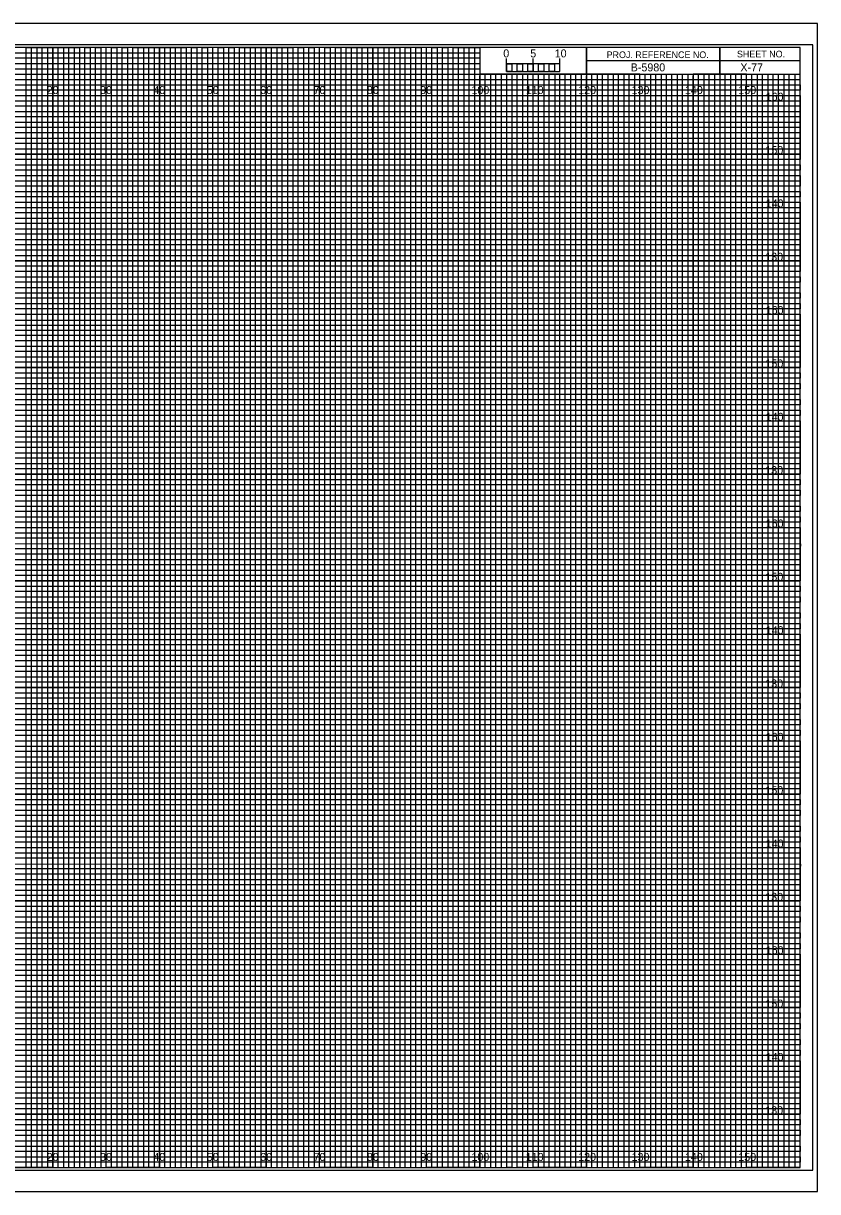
# Model space of a CAD drawing. Extents: x -13 to 323, y -5 to 434.
# Drawn here: x 174.5 to 323.3, y -4.5 to 214.5 of the extents above; entities that cross this region are included whole.
import ezdxf

# ---------------------------------------------------------------- set-up
doc = ezdxf.new("R2010")
doc.units = 0
for name, color, linetype in [('Exist Cross Section Cell', 7, 'Continuous'), ('Exist XS Center Line Elevation Label', 7, 'Continuous'), ('Exist XS Ground Line', 7, 'Continuous'), ('Prop CMT Guardrail Widen Shoulder', 7, 'Continuous'), ('Prop CMT Pvmt Course 1', 7, 'Continuous'), ('Prop CMT Pvmt Course 2', 7, 'Continuous'), ('Prop CMT Pvmt Course 3', 7, 'Continuous'), ('Prop CMT Pvmt Surface', 7, 'Continuous'), ('Prop CMT Pvmt Surface Shoulder', 7, 'Continuous'), ('Prop CMT Shld Paved Course 1', 7, 'Continuous'), ('Prop CMT Shld Paved Course 2', 7, 'Continuous'), ('Prop CMT Shld Paved Course 3', 7, 'Continuous'), ('Prop CMT Subgrade Earthwork', 7, 'Continuous'), ('Prop XS SE Text', 7, 'Continuous'), ('Scratch_Level_0', 7, 'Continuous')]:
    doc.layers.add(name, color=color, linetype=linetype)

msp = doc.modelspace()

# ---------------------------------------------------------------- linework, layer by layer
at = {"layer": 'Exist XS Center Line Elevation Label'}
for points in [[(165, 0), (175, 0), (175, 210), (185, 210), (185, 0), (195, 0), (195, 210), (205, 210), (205, 0), (215, 0), (215, 210), (225, 210), (225, 0), (235, 0), (235, 210), (245, 210), (245, 0), (255, 0), (255, 210), (259.93, 210), (260, 210), (260, 205), (264.99, 205), (264.99, 0), (275, 0), (275, 205), (285, 205), (285, 0), (295, 0), (295, 205), (305, 205), (305, 0), (315, 0), (315, 205)], [(0, 205), (275, 205)], [(0, 185), (320, 185), (320, 195), (0, 195)], [(0, 165), (320, 165), (320, 175), (0, 175)], [(0, 145), (320, 145), (320, 155), (0, 155)], [(0, 125), (320, 125), (320, 135), (0, 135)], [(0, 105), (320, 105), (320, 115), (0, 115)], [(0, 85), (320, 85), (320, 95), (0, 95)], [(0, 65), (320, 65), (320, 75), (0, 75)], [(0, 45), (320, 45), (320, 55), (0, 55)], [(0, 25), (320, 25), (320, 35), (0, 35)], [(0, 5), (320, 5), (320, 15), (0, 15)]]:
    msp.add_lwpolyline(points, dxfattribs=at)
at = {"layer": 'Exist XS Ground Line'}
for p, q in [((190, 210), (180, 210)), ((180, 210), (180, 0)), ((190, 0), (190, 210)), ((210, 210), (200, 210)), ((200, 210), (200, 0)), ((210, 0), (210, 210)), ((230, 210), (220, 210)), ((220, 210), (220, 0)), ((230, 0), (230, 210)), ((250, 210), (240, 210)), ((240, 210), (240, 0)), ((250, 0), (250, 210)), ((260, 210), (260, 0)), ((270, 0), (270, 205)), ((290, 205), (280, 205)), ((280, 205), (280, 0)), ((290, 0), (290, 205)), ((310, 205), (300, 205)), ((300, 205), (300, 0)), ((310, 0), (310, 205)), ((180, 0), (170, 0)), ((200, 0), (190, 0)), ((220, 0), (210, 0)), ((240, 0), (230, 0)), ((260, 0), (250, 0)), ((280, 0), (270, 0)), ((300, 0), (290, 0)), ((320, 0), (310, 0)), ((320, 0), (320, 0))]:
    msp.add_line(p, q, dxfattribs=at)
for points in [[(0, 200), (320, 200), (320, 190), (0, 190)], [(0, 180), (320, 180), (320, 170), (0, 170)], [(0, 160), (320, 160), (320, 150), (0, 150)], [(0, 140), (320, 140), (320, 130), (0, 130)], [(0, 120), (320, 120), (320, 110), (0, 110)], [(0, 100), (320, 100), (320, 90), (0, 90)], [(0, 80), (320, 80), (320, 70), (0, 70)], [(0, 60), (320, 60), (320, 50), (0, 50)], [(0, 40), (320, 40), (320, 30), (0, 30)], [(0, 20), (320, 20), (320, 10), (0, 10)]]:
    msp.add_lwpolyline(points, dxfattribs=at)
at = {"layer": 'Prop CMT Pvmt Course 2'}
for p, q in [((265, 205.49), (265, 207.9)), ((265, 206.9), (265, 207.9)), ((270, 205.49), (270, 207.9)), ((275, 205.49), (275, 207.9)), ((275, 206.9), (275, 207.9))]:
    msp.add_line(p, q, dxfattribs=at)
for points in [[(275, 206.9), (265, 206.9), (265, 205.49), (275, 205.49)], [(265, 206.9), (266, 206.9), (266, 205.49), (265, 205.49)], [(267, 206.9), (268, 206.9), (268, 205.49), (267, 205.49)], [(269, 206.9), (270, 206.9), (270, 205.49), (269, 205.49)], [(271, 206.9), (272, 206.9), (272, 205.49), (271, 205.49)], [(273, 206.9), (274, 206.9), (274, 205.49), (273, 205.49)]]:
    msp.add_lwpolyline(points, close=True, dxfattribs=at)
at = {"layer": 'Prop CMT Pvmt Course 3'}
msp.add_lwpolyline([(-13.4, -4.5), (323.3, -4.5), (323.3, 214.5), (-13.4, 214.5)], close=True, dxfattribs=at)
at = {"layer": 'Prop CMT Pvmt Surface'}
for p, q in [((180, 0), (180, 210)), ((190, 0), (190, 210)), ((200, 0), (200, 210)), ((210, 0), (210, 210)), ((220, 0), (220, 210)), ((230, 0), (230, 210)), ((240, 0), (240, 210)), ((250, 0), (250, 210)), ((260, 0), (260, 204.69)), ((270, 0), (270, 204.69)), ((280, 0), (280, 204.69)), ((290, 0), (290, 204.69)), ((300, 0), (300, 204.69)), ((310, 0), (310, 204.69)), ((0, 200), (320, 200)), ((0, 190), (320, 190)), ((0, 180), (320, 180)), ((0, 170), (320, 170)), ((0, 160), (320, 160)), ((0, 150), (320, 150)), ((0, 140), (320, 140)), ((0, 130), (320, 130)), ((0, 120), (320, 120)), ((0, 110), (320, 110)), ((0, 100), (320, 100)), ((0, 90), (320, 90)), ((0, 80), (320, 80)), ((0, 70), (320, 70)), ((0, 60), (320, 60)), ((0, 50), (320, 50)), ((0, 40), (320, 40)), ((0, 30), (320, 30)), ((0, 20), (320, 20)), ((0, 10), (320, 10))]:
    msp.add_line(p, q, dxfattribs=at)
at = {"layer": 'Prop CMT Pvmt Surface Shoulder'}
for p, q in [((323.3, 214.5), (-13.4, 214.5)), ((-13.4, -4.5), (323.3, -4.5))]:
    msp.add_line(p, q, dxfattribs=at)
at = {"layer": 'Prop CMT Shld Paved Course 1'}
for p, q in [((0, 209), (260, 209)), ((260, 209), (260, 207.98)), ((260, 207.98), (0, 207.98)), ((0, 207), (260, 207)), ((260, 205.89), (0, 205.89)), ((260, 207), (260, 205.89)), ((0, 204), (320, 204))]:
    msp.add_line(p, q, dxfattribs=at)
for points in [[(0, 203), (270, 203), (320, 203), (320, 202), (0, 202)], [(0, 201), (320, 201), (320, 199), (0, 199)], [(0, 198), (320, 198), (320, 197), (0, 196.98)], [(0, 196), (320, 196), (320, 194), (0, 194)], [(0, 193), (320, 193), (320, 192), (0, 192)], [(0, 191), (320, 191), (320, 189), (0, 189)], [(0, 188), (320, 188), (320, 187), (0, 187)], [(0, 186), (320, 186), (320, 184), (0, 184)], [(0, 183), (320, 183), (320, 182), (0, 182)], [(0, 181), (320, 181), (320, 179), (0, 179)], [(0, 178), (320, 178), (320, 177), (0, 177)], [(0, 176), (320, 176), (320, 173.95), (320, 173), (320, 172), (0, 172)], [(0, 174), (320, 174), (320, 173), (0, 173)], [(0, 171), (320, 171), (320, 169), (0, 169.03)], [(0, 169.03), (320, 169), (320, 168), (0, 168)], [(0, 167), (320, 167), (320, 166), (0, 166)], [(0, 164), (320, 164), (320, 163), (0, 163)], [(0, 162), (320, 162), (320, 161), (0, 161)], [(-0.07, 158.89), (320, 158.89), (320, 157.88), (-0.07, 157.88)], [(0, 157), (320, 157), (320, 156), (0, 156)], [(0, 154), (320, 154), (320, 153), (0, 153)], [(0, 152), (320, 152), (320, 151), (0, 151)], [(0, 149), (320, 149), (320, 148), (0, 148)], [(0, 147), (320, 147), (320, 146), (0, 146)], [(0, 144), (320, 144), (320, 143), (0, 143)], [(0, 142), (320, 142), (320, 141), (0, 141)], [(0, 139), (320, 139), (319.99, 137.98), (0, 138)], [(0, 137), (320, 137), (320, 136), (0, 136)], [(0, 134), (320, 134), (320, 133), (0, 133)], [(0, 132), (320, 132), (320, 131), (0, 131)], [(0, 129), (320, 129), (320, 128), (0, 128)], [(0, 127), (320, 127), (320, 126), (0, 126)], [(0, 124), (320, 124), (320, 123), (0, 123)], [(0, 122), (320, 122), (320, 121), (0, 121)], [(0, 119), (320, 119), (320, 118), (0, 118)], [(0, 116.99), (320.07, 116.91), (320, 116), (0, 116)], [(0, 114), (320, 114), (320, 113), (0, 113)], [(0, 112), (320, 112), (320, 111), (0, 111)], [(0, 109), (320, 109), (320, 108), (0, 108)], [(0, 107), (320, 107), (320, 106), (0, 106)], [(0, 104), (320, 104), (320, 103), (0, 103)], [(0, 102), (320, 102), (320, 101), (0, 101)], [(0, 99), (320, 99), (320, 98), (0, 98)], [(0, 97), (320, 97), (320, 96), (0, 96)], [(0, 94), (320, 94), (320, 93), (0, 93)], [(0, 92), (320, 92), (320, 91), (0, 91)], [(0, 89), (320, 89), (320, 88), (0, 88)], [(0, 87), (320, 87), (320, 86), (0, 86)], [(0, 84), (320, 84), (320, 83), (0, 83)], [(0, 82), (320, 82), (320, 81), (0, 81)], [(0, 79), (320, 79), (319.99, 77.98), (0, 78)], [(0, 77), (320, 77), (320, 76), (0, 76)], [(0, 74), (320, 74), (320, 73), (0, 73)], [(0, 72), (320, 72), (320, 71), (0, 71)], [(0, 69), (320, 69), (320, 68), (0, 68)], [(0, 67), (320, 67), (320, 66), (0, 66)], [(0, 64), (320, 64), (320, 63), (0, 63)], [(0, 62), (320, 62), (320, 61), (0, 61)], [(0, 59), (320, 59), (320, 58), (0, 58)], [(0, 56.99), (320.07, 56.91), (320, 56), (0, 56)], [(0, 54), (320, 54), (320, 53), (0, 53)], [(0, 52), (320, 52), (320, 51), (0, 51)], [(0, 49), (320, 49), (320, 48), (0, 48)], [(0, 47), (320, 47), (320, 46), (0, 46)], [(0, 44), (320, 44), (320, 43), (0, 43)], [(0, 42), (320, 42), (320, 41), (0, 41)], [(0, 39), (320, 39), (320, 38), (0, 38)], [(0, 37), (320, 37), (320, 36), (0, 36)], [(0, 34), (320, 34), (320, 33), (0, 33)], [(0, 32), (320, 32), (320, 31), (0, 31)], [(0, 29), (320, 29), (320, 28), (0, 28)], [(0, 27), (320, 27), (320, 26), (0, 26)], [(0, 24), (320, 24), (320, 23), (0, 23)], [(0, 22), (320, 22), (320, 21), (0, 21)], [(0, 19), (320, 19), (320, 18), (0, 18)], [(0, 17), (320, 17), (320, 16), (0, 16)], [(0, 14), (320, 14), (320, 13), (0, 13)], [(0, 12), (320, 12), (320, 11), (0, 11)], [(0, 9), (320, 9), (320, 8), (0, 8)], [(0, 7), (320, 7), (320, 6), (0, 6)], [(0, 4), (320, 4), (320, 3), (0, 3)], [(0, 2), (320, 2), (320, 1), (0, 1)]]:
    msp.add_lwpolyline(points, dxfattribs=at)
at = {"layer": 'Prop CMT Shld Paved Course 2'}
for p, q in [((305, 210), (305, 205)), ((305, 205), (305, 210)), ((280, 207.5), (280, 205)), ((320, 207.49), (280, 207.49)), ((280, 205), (320, 205))]:
    msp.add_line(p, q, dxfattribs=at)
for points in [[(320, 210), (0, 210), (0, 0), (320, 0)], [(280, 210), (260, 210), (260, 205.03), (280, 205.03)], [(320, 210), (280, 210), (280, 205), (320, 205)]]:
    msp.add_lwpolyline(points, close=True, dxfattribs=at)
at = {"layer": 'Prop CMT Shld Paved Course 3'}
for p, q in [((267, 205), (266.01, 205)), ((266.01, 205), (266.01, 0)), ((267, 0), (267, 205)), ((269, 205), (268, 205)), ((268, 205), (268, 0)), ((269, 0), (269, 205)), ((266.01, 0), (265, 0)), ((268, 0), (267, 0))]:
    msp.add_line(p, q, dxfattribs=at)
for points in [[(175, 0), (176, 0), (176, 210), (177, 210), (177, 0)], [(177, 0), (178, 0), (178, 210), (179, 210), (179, 0)], [(180, 0), (181, 0), (181, 210), (182, 210), (182, 0)], [(182, 0), (183, 0), (183, 210), (184, 210), (184, 0)], [(185, 0), (186, 0), (186, 210), (187, 210), (187, 0)], [(187, 0), (188, 0), (188, 210), (189, 210), (189, 0)], [(190, 0), (191, 0), (191, 210), (192, 210), (192, 0)], [(192, 0), (193, 0), (193, 210), (194, 210), (194, 0)], [(195, 0), (196, 0), (196, 210), (197, 210), (197, 0)], [(197, 0), (198, 0), (198, 210), (199, 210), (199, 0)], [(200, 0), (201, 0), (201, 210), (202, 210), (202, 0)], [(202, 0), (203, 0), (203, 210), (204, 210), (204, 0)], [(205, 0), (206, 0), (206, 210), (207, 210), (207, 0)], [(207, 0), (208, 0), (208, 210), (209, 210), (209, 0)], [(210, 0), (211, 0), (211, 210), (212, 210), (212, 0)], [(212, 0), (213, 0), (213, 210), (214, 210), (214, 0)], [(215, 0), (216, 0), (216, 210), (217, 210), (217, 0)], [(217, 0), (218, 0), (218, 210), (219, 210), (219, 0)], [(220, 0), (221, 0), (221, 210), (222, 210), (222, 0)], [(222, 0), (223, 0), (223, 210), (224, 210), (224, 0)], [(225, 0), (226, 0), (226, 210), (227, 210), (227, 0)], [(227, 0), (228, 0), (228, 210), (229, 210), (229, 0)], [(230, 0), (231, 0), (231, 210), (232, 210), (232, 0)], [(232, 0), (233, 0), (233, 210), (234, 210), (234, 0)], [(235, 0), (236, 0), (236, 210), (237, 210), (237, 0)], [(237, 0), (238, 0), (238, 210), (239, 210), (239, 0)], [(240, 0), (241, 0), (241, 210), (242, 210), (242, 0)], [(242, 0), (243, 0), (243, 210), (244, 210), (244, 0)], [(245, 0), (246, 0), (246, 210), (247, 210), (247, 0)], [(247, 0), (248, 0), (248, 210), (249, 210), (249, 0)], [(250, 0), (251, 0), (251, 210), (252, 210), (252, 0)], [(252, 0), (253, 0), (253, 210), (254, 210), (254, 0)], [(255, 0), (256, 0), (256, 210), (257, 210), (257, 0)], [(257, 0), (258, 0), (258, 210), (259, 210), (259, 0)], [(260, 0), (261, 0), (261, 205), (262.02, 205), (262.02, 0)], [(262, 0), (263, 0), (263, 205), (263.99, 205), (263.99, 0)], [(270, 0), (270.98, 0), (270.98, 205), (272, 205), (272, 0)], [(272, 0), (273, 0), (273, 205), (274.05, 205), (274.05, 0)], [(275, 0), (276, 0), (276, 205), (277, 205), (277, 0)], [(277, 0), (278, 0), (278, 205), (279, 205), (279, 0)], [(280, 0), (281, 0), (281, 205), (282, 205), (282, 0)], [(282, 0), (283, 0), (283, 205), (284, 205), (284, 0)], [(285, 0), (286, 0), (286, 205), (287, 205), (287, 0)], [(287, 0), (288, 0), (288, 205), (289, 205), (289, 0)], [(290, 0), (291, 0), (291, 205), (292, 205), (292, 0)], [(292, 0), (293, 0), (293, 205), (294, 205), (294, 0)], [(295, 0), (296, 0), (296, 205), (297, 205), (297, 0)], [(297, 0), (298, 0), (298, 205), (299, 205), (299, 0)], [(300, 0), (301, 0), (301, 205), (302, 205), (302, 0)], [(302, 0), (303, 0), (303, 205), (304, 205), (304, 0)], [(305, 0), (306, 0), (306, 205), (307, 205), (307, 0)], [(307, 0), (308, 0), (308, 205), (309, 205), (309, 0)], [(310, 0), (311, 0), (311, 205), (312, 205), (312, 0)], [(312, 0), (313, 0), (313, 205), (314, 205), (314, 0)], [(315, 0), (316, 0), (316, 205), (317, 205), (317, 0)], [(317, 0), (318, 0), (318, 205), (319, 205), (319, 0)]]:
    msp.add_lwpolyline(points, dxfattribs=at)
at = {"layer": 'Prop CMT Subgrade Earthwork'}
msp.add_lwpolyline([(-10.8, -0.5), (322.4, -0.5), (322.4, 210.5), (-10.8, 210.5)], close=True, dxfattribs=at)

# ---------------------------------------------------------------- texts
at = {"layer": 'Exist Cross Section Cell'}
for s, p in [('20', (178.86, 201.25)), ('30', (188.86, 201.25)), ('40', (198.86, 201.25)), ('50', (208.86, 201.25)), ('60', (218.86, 201.25)), ('70', (228.86, 201.25)), ('80', (238.86, 201.25)), ('90', (248.86, 201.25)), ('100', (258.44, 201.25)), ('110', (268.62, 201.25)), ('120', (278.44, 201.25)), ('130', (288.44, 201.25)), ('140', (298.44, 201.25)), ('150', (308.44, 201.25)), ('20', (178.86, 1.25)), ('30', (188.86, 1.25)), ('40', (198.86, 1.25)), ('50', (208.86, 1.25)), ('60', (218.86, 1.25)), ('70', (228.86, 1.25)), ('80', (238.86, 1.25)), ('90', (248.86, 1.25)), ('100', (258.44, 1.25)), ('110', (268.62, 1.25)), ('120', (278.44, 1.25)), ('130', (288.44, 1.25)), ('140', (298.44, 1.25)), ('150', (308.44, 1.25))]:
    msp.add_text(s, height=1.5, dxfattribs=at).set_placement(p)
at = {"layer": 'Prop CMT Guardrail Widen Shoulder'}
msp.add_text('X-77', height=1.5, dxfattribs=at).set_placement((308.83, 205.5))
at = {"layer": 'Prop CMT Pvmt Course 1'}
for s, p in [('160', (313.57, 200)), ('150', (313.52, 190)), ('140', (313.57, 180)), ('130', (313.49, 170)), ('160', (313.57, 160)), ('150', (313.52, 150)), ('140', (313.57, 140)), ('130', (313.49, 130)), ('160', (313.57, 120)), ('150', (313.52, 110)), ('140', (313.57, 100)), ('130', (313.49, 90)), ('160', (313.57, 80)), ('150', (313.52, 70)), ('140', (313.57, 60)), ('130', (313.49, 50)), ('160', (313.57, 40)), ('150', (313.52, 30)), ('140', (313.57, 20)), ('130', (313.49, 10))]:
    msp.add_text(s, height=1.5, dxfattribs=at).set_placement(p)
at = {"layer": 'Prop CMT Pvmt Course 2'}
msp.add_text('0', height=1.5, dxfattribs=at).set_placement((264.41, 208.12))
at = {"layer": 'Prop CMT Shld Paved Course 2'}
for s, p in [('PROJ. REFERENCE NO.', (283.77, 207.99)), ('SHEET NO.', (308.19, 208.12))]:
    msp.add_text(s, height=1.25, dxfattribs=at).set_placement(p)
at = {"layer": 'Prop XS SE Text'}
for s, p in [('5', (269.47, 208.12)), ('10', (274.04, 208.12))]:
    msp.add_text(s, height=1.5, dxfattribs=at).set_placement(p)
at = {"layer": 'Scratch_Level_0'}
msp.add_text('B-5980', height=1.5, dxfattribs=at).set_placement((288.28, 205.5))

doc.saveas('drawing.dxf')
